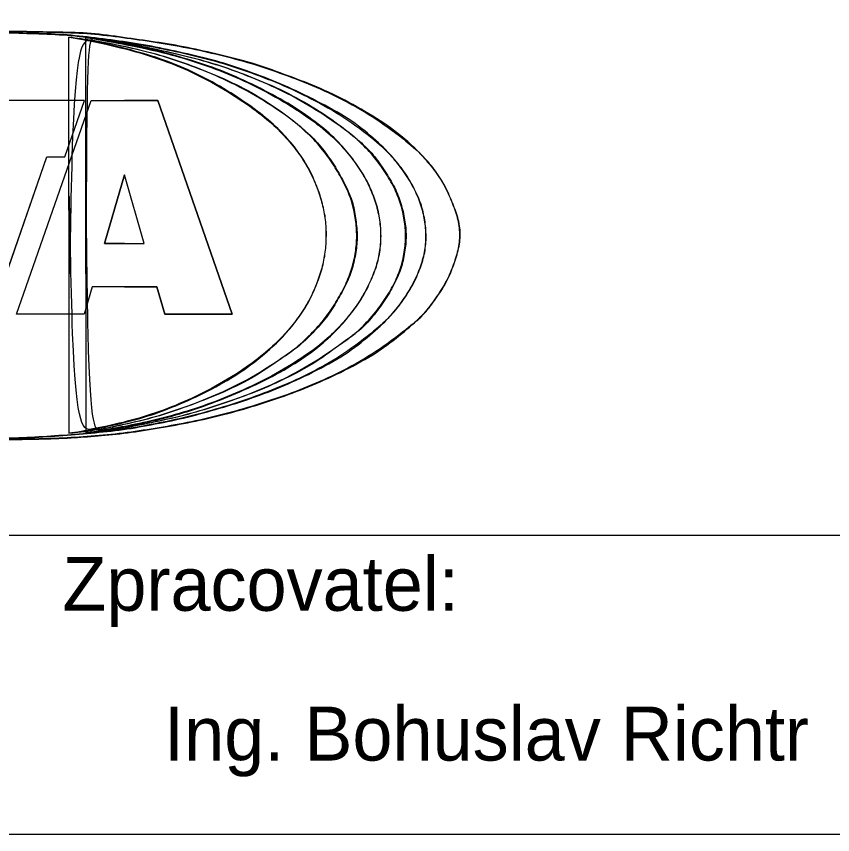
# Model space of a CAD drawing. Extents: x 25 to 46, y -90 to -60.3.
# Drawn here: x 40.036 to 42.763, y -79.8 to -77.068 of the extents above; entities that cross this region are included whole.
import ezdxf

# ---------------------------------------------------------------- set-up
doc = ezdxf.new("R2010")
doc.units = 0
doc.layers.add('_popis', color=7, linetype='Continuous')
doc.layers.add('Rozpiska_pole_6', color=7, linetype='Continuous')

msp = doc.modelspace()

# ---------------------------------------------------------------- linework, layer by layer
at = {"layer": '_popis'}
for p, q in [((40.2641, -77.3488), (39.825, -77.3488)), ((40.037, -78.0626), (40.2855, -77.3488)), ((40.1984, -77.5375), (40.2641, -77.3488)), ((40.2855, -77.3488), (40.3969, -77.3488)), ((40.3969, -77.3488), (40.5083, -77.3488)), ((40.5083, -77.3488), (40.7567, -78.0626)), ((39.9551, -78.0628), (40.1379, -77.5375)), ((40.1379, -77.5375), (40.1984, -77.5375)), ((40.3969, -77.5973), (40.3305, -77.8269)), ((40.4633, -77.8269), (40.3969, -77.5973)), ((40.3305, -77.8269), (40.3969, -77.8269)), ((40.3969, -77.8269), (40.4633, -77.8269)), ((40.2887, -77.9716), (40.2623, -78.0628)), ((40.3969, -77.9716), (40.2887, -77.9716)), ((40.5051, -77.9716), (40.3969, -77.9716)), ((40.5315, -78.0628), (40.5051, -77.9716)), ((40.2623, -78.0628), (40.037, -78.0626)), ((40.7567, -78.0626), (40.5315, -78.0628))]:
    msp.add_line(p, q, dxfattribs=at)
for points in [[(39.825, -77.3488), (39.7594, -77.5375), (39.8369, -77.5375), (39.7381, -77.8213), (39.8222, -78.0628), (39.9551, -78.0628), (40.1379, -77.5375), (40.1984, -77.5375), (40.2641, -77.3488), (39.825, -77.3488)], [(40.3969, -77.9716), (40.2887, -77.9716), (40.2623, -78.0628), (40.037, -78.0626), (40.2855, -77.3488), (40.3969, -77.3488)], [(40.3969, -77.9716), (40.5051, -77.9716), (40.5315, -78.0628), (40.7567, -78.0626), (40.5083, -77.3488), (40.3969, -77.3488)], [(40.3969, -77.8269), (40.3305, -77.8269), (40.3969, -77.5973)], [(40.3969, -77.8269), (40.4633, -77.8269), (40.3969, -77.5973)]]:
    msp.add_lwpolyline(points, dxfattribs=at)
for points in [[(39.9639, -77.1182), (39.9235, -77.1188), (39.852, -77.1199), (39.7448, -77.1208), (39.642, -77.1242), (39.5347, -77.1357), (39.4277, -77.1537), (39.3201, -77.1713), (39.2128, -77.1946), (39.1051, -77.2223), (38.9975, -77.2573), (38.8906, -77.3005), (38.7817, -77.3493), (38.6736, -77.4136), (38.589, -77.4768), (38.5246, -77.5353), (38.4849, -77.5846), (38.452, -77.639), (38.4265, -77.6924), (38.4148, -77.7474), (38.4067, -77.8011), (38.4133, -77.8559), (38.4303, -77.9096), (38.4542, -77.9643), (38.4893, -78.0177), (38.5268, -78.0666), (38.5904, -78.1238), (38.6724, -78.1873), (38.7823, -78.2472), (38.8896, -78.2978), (38.9979, -78.3377), (39.1054, -78.3729), (39.2125, -78.4023), (39.3197, -78.4256), (39.427, -78.4454), (39.5348, -78.4603), (39.6419, -78.4721), (39.7493, -78.4805), (39.8565, -78.4792), (39.9639, -78.483), (40.0712, -78.4798), (40.1532, -78.4786), (40.1993, -78.4763), (40.2097, -78.4757)], [(39.9639, -77.1182), (39.8427, -77.1199), (39.7495, -77.1211), (39.6423, -77.1255), (39.5351, -77.1368), (39.4279, -77.1536), (39.3205, -77.1722), (39.2133, -77.1952), (39.1061, -77.2232), (38.9987, -77.2583), (38.8915, -77.3009), (38.7849, -77.3503), (38.6775, -77.4138), (38.5703, -77.4945), (38.5286, -77.5334), (38.4849, -77.5873), (38.4523, -77.6406), (38.4282, -77.6944), (38.4153, -77.7478), (38.4091, -77.8015), (38.4147, -77.8543), (38.431, -77.9085), (38.4551, -77.9623), (38.4888, -78.0156), (38.532, -78.0694), (38.5702, -78.1052), (38.6774, -78.1865), (38.7846, -78.2471), (38.8906, -78.2964), (38.9989, -78.3373), (39.1065, -78.3723), (39.2131, -78.4014), (39.3197, -78.425), (39.4275, -78.4446), (39.535, -78.4598), (39.6427, -78.4716), (39.7487, -78.4789), (39.8568, -78.4801), (39.9639, -78.4818), (40.0711, -78.4801), (40.1786, -78.4773), (40.2858, -78.4705), (40.3924, -78.4605), (40.4999, -78.4442), (40.6071, -78.4251), (40.7143, -78.401), (40.8218, -78.3713), (40.929, -78.336), (41.0362, -78.2945), (41.1428, -78.2446), (41.2508, -78.1813), (41.3585, -78.0978), (41.3905, -78.0692), (41.4326, -78.0159), (41.468, -77.9626), (41.4928, -77.9085), (41.5102, -77.8552), (41.5187, -77.8015), (41.5124, -77.748), (41.4939, -77.6942), (41.4698, -77.6394), (41.4378, -77.5872), (41.3924, -77.5334), (41.3593, -77.5009), (41.2509, -77.417), (41.1437, -77.3537), (41.0373, -77.3029), (40.9295, -77.2614), (40.8218, -77.2244), (40.7152, -77.1964), (40.6071, -77.1722), (40.4994, -77.1537), (40.3917, -77.1386), (40.2853, -77.125), (40.1784, -77.1211), (40.0713, -77.1192), (39.9639, -77.1182), (39.9639, -77.1182), (39.9639, -77.1182)], [(40.2097, -78.4757), (40.235, -78.4743), (40.296, -78.4699), (40.3931, -78.4618), (40.5, -78.4443), (40.6076, -78.426), (40.715, -78.4017), (40.8225, -78.3721), (40.93, -78.3366), (41.0376, -78.2954), (41.1457, -78.2449), (41.256, -78.1823), (41.3346, -78.1179), (41.398, -78.0648), (41.4318, -78.0169), (41.4691, -77.965), (41.4932, -77.9098), (41.5113, -77.8562), (41.5216, -77.8018), (41.5143, -77.7463), (41.4938, -77.6932), (41.471, -77.6383), (41.4374, -77.5837), (41.3984, -77.5387), (41.3381, -77.4793), (41.2557, -77.4172), (41.1464, -77.3533), (41.0387, -77.3015), (40.9301, -77.2615), (40.8235, -77.2229), (40.7151, -77.1961), (40.6078, -77.1712), (40.4996, -77.1531), (40.3922, -77.1391), (40.2856, -77.1225), (40.1783, -77.1213), (40.0712, -77.119), (39.9997, -77.1184), (39.9639, -77.1182)], [(39.9639, -77.1211), (39.9997, -77.1226), (40.0713, -77.1255), (40.1787, -77.1265), (40.2858, -77.1383), (40.393, -77.1519), (40.5005, -77.1698), (40.6076, -77.1935), (40.7158, -77.2191), (40.8227, -77.2556), (40.9309, -77.2969), (41.0378, -77.3497), (41.1493, -77.4096), (41.2316, -77.4752), (41.2925, -77.5363), (41.331, -77.5848), (41.364, -77.639), (41.3885, -77.6928), (41.4013, -77.7476), (41.406, -77.8017), (41.4019, -77.8563), (41.3856, -77.9101), (41.3615, -77.9642), (41.3273, -78.0178), (41.2909, -78.0655), (41.2291, -78.1234), (41.1493, -78.1893), (41.0386, -78.2517), (40.9304, -78.3018), (40.8228, -78.3436), (40.715, -78.3773), (40.6078, -78.4072), (40.5001, -78.4295), (40.393, -78.4491), (40.2855, -78.4596), (40.1784, -78.4688), (40.0713, -78.4757), (39.9639, -78.4792), (39.8566, -78.4751), (39.7494, -78.4675), (39.6419, -78.4616), (39.5346, -78.4489), (39.4272, -78.4315), (39.3199, -78.4087), (39.2119, -78.3821), (39.1053, -78.3453), (38.9969, -78.3064), (38.8884, -78.2571), (38.7805, -78.1918), (38.696, -78.1276), (38.6313, -78.0686), (38.5928, -78.0182), (38.5608, -77.9637), (38.5367, -77.9099), (38.5218, -77.8558), (38.5123, -77.8015), (38.5206, -77.7471), (38.5345, -77.693), (38.5572, -77.6389), (38.589, -77.5849), (38.6276, -77.5322), (38.6946, -77.4726), (38.7792, -77.4054), (38.8901, -77.3461), (38.997, -77.2943), (39.1048, -77.2523), (39.2124, -77.218), (39.32, -77.1904), (39.4116, -77.1723), (39.4832, -77.1591), (39.5546, -77.1477), (39.6419, -77.1348), (39.7494, -77.1281), (39.8567, -77.1236), (39.9282, -77.122), (39.9639, -77.1211)], [(39.9639, -77.1211), (39.8567, -77.124), (39.7495, -77.1284), (39.6423, -77.1363), (39.5351, -77.1509), (39.4869, -77.1587), (39.428, -77.1694), (39.3205, -77.1913), (39.2133, -77.2188), (39.1059, -77.2532), (38.9988, -77.2952), (38.8914, -77.3463), (38.7848, -77.4063), (38.6775, -77.4883), (38.6298, -77.5333), (38.5888, -77.5872), (38.558, -77.6404), (38.5355, -77.6944), (38.5215, -77.7477), (38.5153, -77.8015), (38.5226, -77.8551), (38.5377, -77.9083), (38.5613, -77.9622), (38.5928, -78.0158), (38.6349, -78.0696), (38.6775, -78.11), (38.7847, -78.1919), (38.8914, -78.256), (38.9986, -78.3054), (39.1058, -78.3452), (39.2132, -78.3807), (39.3204, -78.4082), (39.4276, -78.4306), (39.535, -78.4482), (39.6422, -78.4605), (39.7494, -78.4678), (39.8567, -78.4745), (39.9639, -78.4779), (40.0711, -78.4751), (40.1786, -78.4684), (40.2852, -78.4594), (40.3924, -78.4476), (40.4999, -78.4291), (40.607, -78.4061), (40.7142, -78.3769), (40.8217, -78.3426), (40.9289, -78.3011), (41.0361, -78.2512), (41.1435, -78.1886), (41.2507, -78.1028), (41.285, -78.0695), (41.3277, -78.0156), (41.3608, -77.9624), (41.3849, -77.9085), (41.4, -77.8553), (41.4045, -77.802), (41.4, -77.7479), (41.3871, -77.6947), (41.3636, -77.6408), (41.331, -77.5872), (41.2883, -77.5333), (41.2507, -77.4952), (41.1436, -77.4105), (41.0362, -77.3496), (40.929, -77.298), (40.8218, -77.256), (40.7144, -77.2206), (40.6073, -77.1937), (40.5001, -77.1707), (40.3926, -77.1526), (40.2855, -77.1385), (40.1786, -77.1283), (40.0714, -77.1249), (39.9639, -77.1211), (39.9639, -77.1211), (39.9639, -77.1211)], [(40.2117, -77.1377), (40.2364, -77.1406), (40.2974, -77.1475), (40.3936, -77.1674), (40.5016, -77.1919), (40.6087, -77.2272), (40.7165, -77.2692), (40.8252, -77.3224), (40.9096, -77.3777), (40.9794, -77.4304), (41.0306, -77.476), (41.076, -77.5308), (41.1108, -77.5858), (41.1395, -77.6393), (41.1617, -77.6929), (41.1701, -77.7476), (41.1766, -77.8017), (41.1706, -77.8559), (41.1592, -77.9101), (41.1385, -77.964), (41.1078, -78.0165), (41.0746, -78.0728), (41.026, -78.1253), (40.9786, -78.1723), (40.9068, -78.2196), (40.826, -78.2769), (40.7163, -78.3288), (40.6081, -78.3704), (40.5013, -78.4074), (40.3931, -78.4318), (40.2975, -78.4523), (40.2364, -78.4575), (40.2118, -78.4596)], [(40.2118, -78.4596), (40.2364, -78.4557), (40.2969, -78.446), (40.3936, -78.4259), (40.502, -78.3958), (40.6095, -78.352), (40.7178, -78.2985), (40.8116, -78.2399), (40.8852, -78.1786), (40.9392, -78.1254), (40.9819, -78.0711), (41.0158, -78.0178), (41.0394, -77.9631), (41.0585, -77.9097), (41.069, -77.8555), (41.0721, -77.8015), (41.0705, -77.7474), (41.0592, -77.6935), (41.0419, -77.6396), (41.0186, -77.5853), (40.9863, -77.531), (40.9437, -77.4775), (40.8896, -77.4217), (40.8123, -77.3622), (40.7178, -77.3004), (40.6099, -77.2449), (40.5018, -77.2027), (40.3933, -77.1738), (40.2973, -77.1502), (40.2364, -77.1413), (40.2117, -77.1377)], [(40.2117, -77.1377), (40.2855, -77.1494), (40.3926, -77.174), (40.5002, -77.2044), (40.6073, -77.2459), (40.7146, -77.3011), (40.8217, -77.3706), (40.8921, -77.4266), (40.9442, -77.4798), (40.9863, -77.5336), (41.0179, -77.5869), (41.0413, -77.6407), (41.0584, -77.6943), (41.069, -77.7481), (41.0713, -77.8013), (41.0678, -77.8551), (41.0573, -77.9089), (41.0391, -77.9621), (41.0151, -78.0157), (40.9817, -78.0695), (40.9402, -78.1221), (40.8863, -78.1762), (40.8219, -78.2294), (40.7148, -78.2978), (40.6075, -78.3513), (40.5005, -78.394), (40.3922, -78.425), (40.2855, -78.4473), (40.2118, -78.4596), (40.2117, -77.1377), (40.2118, -78.4596)], [(40.2118, -78.4596), (40.2855, -78.452), (40.3932, -78.4316), (40.4994, -78.4058), (40.6072, -78.3701), (40.7147, -78.3279), (40.8214, -78.2754), (40.9289, -78.2052), (40.9694, -78.1768), (41.0277, -78.1227), (41.074, -78.0696), (41.1082, -78.0157), (41.1376, -77.9621), (41.1581, -77.9085), (41.1697, -77.856), (41.1745, -77.8017), (41.1698, -77.7475), (41.1598, -77.6945), (41.1393, -77.6412), (41.1104, -77.5866), (41.0762, -77.5335), (41.0315, -77.4796), (40.9726, -77.426), (40.9284, -77.3924), (40.8216, -77.3233), (40.7149, -77.2702), (40.6071, -77.2277), (40.5006, -77.1935), (40.3934, -77.1677), (40.2854, -77.1471), (40.2117, -77.1377), (40.2118, -78.4596), (40.2117, -77.1377)], [(40.2677, -78.458), (40.284, -78.4558), (40.3258, -78.4501), (40.4035, -78.4371), (40.5008, -78.4174), (40.6085, -78.3886), (40.7155, -78.3503), (40.8232, -78.3045), (40.932, -78.2499), (41.0253, -78.1891), (41.0971, -78.127), (41.1461, -78.0714), (41.1865, -78.0185), (41.2147, -77.9634), (41.2378, -77.9101), (41.2513, -77.8558), (41.2553, -77.8018), (41.2516, -77.7474), (41.2393, -77.693), (41.2185, -77.6388), (41.1896, -77.5846), (41.1507, -77.5313), (41.1012, -77.4743), (41.0268, -77.412), (40.932, -77.3501), (40.8238, -77.2935), (40.7167, -77.2461), (40.6086, -77.2104), (40.498, -77.18), (40.3844, -77.1566), (40.3067, -77.145), (40.2681, -77.1392)], [(40.2681, -77.1392), (40.2737, -77.1395), (40.3154, -77.142), (40.3929, -77.1558), (40.4999, -77.1771), (40.6081, -77.2014), (40.7162, -77.2305), (40.8231, -77.2712), (40.9318, -77.3167), (41.0404, -77.3779), (41.1211, -77.4345), (41.1851, -77.4867), (41.229, -77.5289), (41.2673, -77.5856), (41.3007, -77.6379), (41.3216, -77.6931), (41.334, -77.7473), (41.3397, -77.8016), (41.3338, -77.8555), (41.3228, -77.9105), (41.2981, -77.9637), (41.2664, -78.0175), (41.2255, -78.072), (41.1853, -78.1172), (41.1176, -78.1619), (41.0414, -78.2219), (40.9319, -78.2806), (40.824, -78.3273), (40.7162, -78.3644), (40.6094, -78.3987), (40.501, -78.4217), (40.408, -78.4409), (40.3303, -78.4528), (40.2882, -78.4563), (40.2677, -78.458)], [(40.2677, -78.458), (40.3292, -78.4522), (40.3933, -78.4427), (40.5006, -78.4217), (40.6083, -78.397), (40.7158, -78.3641), (40.8225, -78.3263), (40.9293, -78.2801), (41.0368, -78.2205), (41.1446, -78.1443), (41.1735, -78.1238), (41.2261, -78.0697), (41.2667, -78.0148), (41.2978, -77.9622), (41.3209, -77.9092), (41.3331, -77.8548), (41.3378, -77.8012), (41.3331, -77.7486), (41.3205, -77.694), (41.2994, -77.64), (41.2679, -77.587), (41.2295, -77.5334), (41.1748, -77.4787), (41.1454, -77.4546), (41.0368, -77.3782), (40.9285, -77.3178), (40.8217, -77.2713), (40.716, -77.2324), (40.6063, -77.2018), (40.5001, -77.1776), (40.3924, -77.1561), (40.2849, -77.1403), (40.2681, -77.1392), (40.2677, -78.458), (40.2681, -77.1392)], [(40.2681, -77.1392), (40.3837, -77.1576), (40.4999, -77.1817), (40.6077, -77.2112), (40.7153, -77.2476), (40.8215, -77.2938), (40.9288, -77.3506), (41.0363, -77.4218), (41.1036, -77.4796), (41.1514, -77.5337), (41.1893, -77.5868), (41.2177, -77.6399), (41.2382, -77.6943), (41.2503, -77.7484), (41.254, -77.8014), (41.2498, -77.8554), (41.2367, -77.9085), (41.2146, -77.9621), (41.1857, -78.0162), (41.1468, -78.0693), (41.0988, -78.1228), (41.0352, -78.1785), (40.929, -78.2489), (40.8213, -78.3041), (40.7142, -78.3496), (40.607, -78.3874), (40.5003, -78.4163), (40.3928, -78.4385), (40.3165, -78.4511), (40.2677, -78.458), (40.2681, -77.1392), (40.2677, -78.458)]]:
    msp.add_open_spline(points, degree=3, dxfattribs=at)
at = {"layer": 'Rozpiska_pole_6'}
msp.add_line((27, -78.8), (44, -78.8), dxfattribs=at)
msp.add_lwpolyline([(27, -74.8), (44, -74.8), (44, -79.8), (27, -79.8)], close=True, dxfattribs=at)

# ---------------------------------------------------------------- texts
for s, p in [('Zpracovatel:', (40.1896, -79.0527)), ('Ing. Bohuslav Richtr', (40.5296, -79.5527))]:
    msp.add_text(s, height=0.18, dxfattribs=at).set_placement(p)

doc.saveas('drawing.dxf')
